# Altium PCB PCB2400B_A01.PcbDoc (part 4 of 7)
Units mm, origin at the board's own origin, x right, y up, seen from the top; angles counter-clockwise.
Board outline 115 x 60 mm, 6 copper layers (Top Layer, Signal Layer 2, Signal Layer 3, Signal Layer 4, Signal Layer 5, Bottom Layer), stack 1.555 mm thick; 382 components, 308 nets, 1384 pads, 1152 vias.
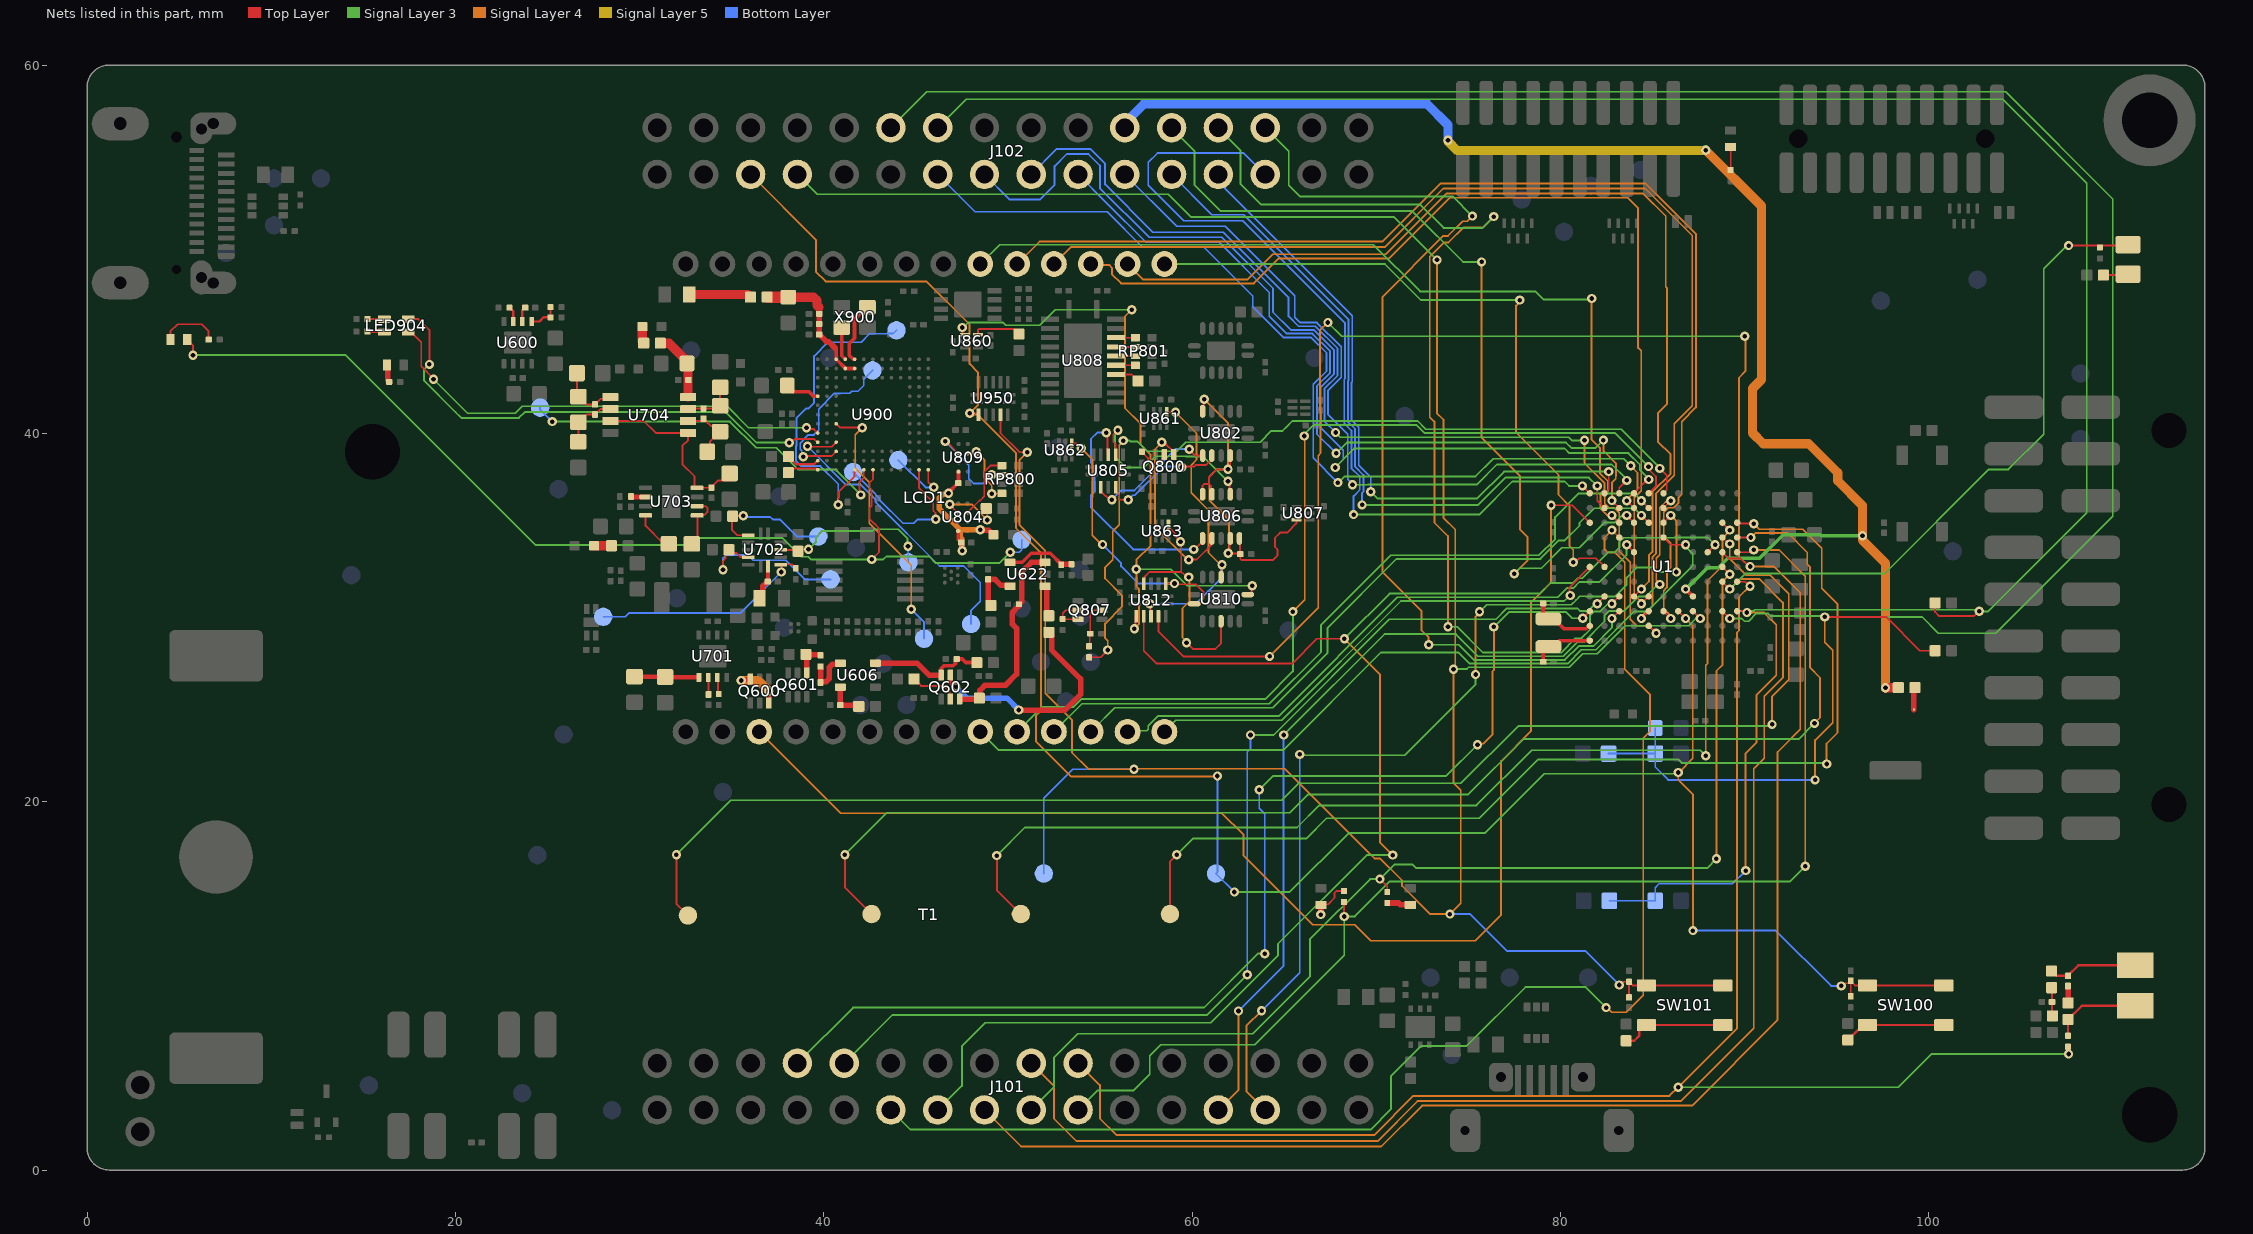
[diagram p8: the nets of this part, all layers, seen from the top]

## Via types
v1: diameter 0.5, hole 0.25, Top Layer to Bottom Layer, tented both sides, 773 vias
v2: diameter 0.508, hole 0.25, Top Layer to Bottom Layer, tented both sides, 379 vias

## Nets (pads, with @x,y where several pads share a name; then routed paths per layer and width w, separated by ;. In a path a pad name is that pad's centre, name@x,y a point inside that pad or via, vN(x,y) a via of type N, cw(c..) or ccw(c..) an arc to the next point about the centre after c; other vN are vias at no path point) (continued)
LCD_SEG14: LCD1.3 U1.C1 | length 72.1
  Top Layer w0.1: v1(79.5,36.1) 80.65,36.1 U1.C1@81.6,35.15
  Signal Layer 4 w0.1: LCD1.3@36.5,23.8 40.925,19.375 61.625,19.375 62.8,18.2 62.8,17.075 66.556,13.319 68.831,13.319 69.697,12.453 75.371,12.453 76.783,13.864 76.783,22.208 78.4,23.825 78.4,30.812 79.5,31.912 v1(79.5,36.1)
LCD_SEG28: LCD1.9 U1.D6 | length 46.4
  Top Layer w0.1: U1.D6@85.6,34.35 86.001,33.951 v1@86.799,33.951 ; v1(86.801,33.95) v1@86.799,33.951 ; v1@86.801,33.951 v1@86.799,33.951
  Signal Layer 3 w0.1: LCD1.9@48.5,23.8 49.493,22.807 64.957,22.807 70.261,28.111 74.464,28.111 75.075,27.5 80.392,27.5 81.142,28.25 81.935,28.25 84.023,30.338 84.713,30.338 87.189,32.814 87.189,33.464 86.801,33.852 v1(86.801,33.95)
LCD_SEG29: LCD1.10 U1.A5 | length 51.2
  Top Layer w0.1: v1(84.789,38.2) 84.7,38.2 84.7,38.15 85.189,37.661 85.189,37.139 U1.A5@84.8,36.75
  Signal Layer 3 w0.1: LCD1.10@50.5,23.8 51.843,25.143 53.56,25.143 53.992,25.575 63.975,25.575 65.475,27.075 v1(65.475,30.325) ; v1(66.098,39.859) 66.098,39.948 66.613,40.463 72.178,40.463 72.613,40.027 82.961,40.027 v1(84.789,38.2)
  Signal Layer 4 w0.1: v1(65.475,30.325) 66.118,30.968 66.118,39.84 v1(66.098,39.859)
LCD_SEG30: LCD1.11 U1.B5 | length 39.7
  Top Layer w0.1: v1(84.4,36.35) U1.B5@84.8,35.95 ; v1(84.4,36.35) 84.469,36.282 v1@84.464,36.295
  Signal Layer 3 w0.1: LCD1.11@52.5,23.8 54.025,25.325 64.2,25.325 67.005,28.13 67.005,29.601 70.79,33.386 78.836,33.386 79.711,34.261 79.711,35.46 80.991,36.74 84.01,36.74 v1(84.4,36.35)
LCD_SEG31: LCD1.12 U1.C5 | length 36.4
  Top Layer w0.1: v1(84.4,35.55) U1.C5@84.8,35.15
  Signal Layer 3 w0.1: LCD1.12@54.575,23.95 54.65,23.95 55.8,25.1 64.375,25.1 67.347,28.072 67.347,29.43 71.103,33.186 78.919,33.186 79.922,34.189 80.239,34.189 81.039,34.989 81.039,35.139 81.839,35.939 84.011,35.939 v1(84.4,35.55)
LCD_SEG32: LCD1.13 U1.E4 | length 32.6
  Top Layer w0.1: v1(83.6,33.95) U1.E4@84,33.55 ; v1(83.6,33.95) 83.669,33.882 83.815,33.735
  Signal Layer 3 w0.1: LCD1.13@56.5,23.8 56.552,23.852 57.552,23.852 57.625,23.925 57.625,24.125 57.7,24.2 ; 57.699,24.201 58.148,24.65 64.7,24.65 71.15,31.1 79.85,31.1 80.35,31.6 80.701,31.6 81.04,31.939 82.14,31.939 83.6,33.4 v1(83.6,33.95)
LCD_SEG33: LCD1.14 U1.F1 | length 27.1
  Top Layer w0.1: v1(80.539,31.2) 80.5,31.2 80.5,31.65 U1.F1@81.6,32.75
  Signal Layer 3 w0.1: LCD1.14@58.5,23.8 59.125,24.425 64.871,24.425 71.346,30.9 80.2,30.9 80.5,31.2 v1(80.539,31.2)
LCD_SEG34: LCD1.15 U1.F2 | length 37.7
  Top Layer w0.1: v1(80.7,33) 80.8,33 81.023,33.223 81.927,33.223 U1.F2@82.4,32.75
  Signal Layer 3 w0.1: LCD1.15@58.5,49.2 70.475,49.2 72.434,47.241 v1(77.794,47.241)
  Signal Layer 4 w0.1: v1(77.794,47.241) 77.794,47.133 77.6,46.939 77.6,40.05 79.9,37.75 79.9,36.676 80.494,36.082 80.494,33.9 80.7,33.694 v1(80.7,33)
LCD_SEG35: LCD1.16 U1.H4 | length 54
  Top Layer w0.1: U1.H4@84,31.15 v1(84.4,31.549)
  Signal Layer 4 w0.1: LCD1.16@56.5,49.2 57.35,48.35 63,48.35 64.384,49.734 70.509,49.734 73.8,53.025 84.504,53.025 85.723,51.806 85.723,47.968 85.789,47.902 85.789,41.589 85.3,41.1 85.3,39.55 85.985,38.865 85.985,37.818 85,36.833 85,33.568 84.81,33.378 84.81,31.959 v1(84.4,31.549)
LCD_SEG36: LCD1.17 U1.H5 | length 55
  Top Layer w0.1: v1@84.4,30.75 U1.H5@84.8,31.15
  Signal Layer 4 w0.1: LCD1.17@54.5,49.2 54.552,49.148 55.502,49.148 55.65,49 55.65,48.65 56.15,48.15 63.36,48.15 64.711,49.501 70.701,49.501 74,52.8 83.653,52.8 84.222,52.231 84.222,44.646 84.389,44.479 84.389,36.895 84.011,36.517 84.011,31.236 84.4,30.846 v1(84.4,30.749)
LCD_SEG37: LCD1.18 U1.J5 | length 59.9
  Top Layer w0.1: v1(84.4,29.949) 84.8,30.349 U1.J5@84.8,30.35
  Signal Layer 4 w0.1: LCD1.18@52.5,49.2 53.42,50.12 70.47,50.12 73.65,53.3 84.609,53.3 87.161,50.749 87.161,41.494 86.185,40.518 86.185,37.735 85.2,36.75 85.2,33.485 85.01,33.295 85.01,30.653 84.4,30.043 v1(84.4,29.949)
LCD_SEG38: LCD1.19 U1.J6 | length 62.6
  Top Layer w0.1: U1.J6@85.6,30.35 v1(86.001,29.949)
  Signal Layer 4 w0.1: LCD1.19@50.5,49.2 51.715,50.415 70.34,50.415 73.5,53.575 84.617,53.575 87.361,50.831 87.361,41.411 86.589,40.639 86.589,36.688 86.412,36.511 86.412,36.211 86.162,35.961 85.862,35.961 85.612,35.711 85.612,34.408 85.988,34.032 85.988,32.729 85.789,32.53 85.789,31.639 85.612,31.462 85.612,30.477 86.001,30.088 v1(86.001,29.949)
LCD_SEG39: LCD1.20 U1.K5 | length 55.8
  Top Layer w0.1: U1.K5@84.799,29.552 U1.K5@84.801,29.551 ; U1.K5@84.8,29.55 v1(85.2,29.149)
  Signal Layer 3 w0.1: LCD1.20@48.5,49.2 49.55,50.25 69.85,50.25 72.387,47.713 78.637,47.713 79.075,47.275 81.65,47.275 v1(81.7,47.325)
  Signal Layer 4 w0.1: v1(81.7,47.325) 81.7,39.659 82.145,39.214 82.145,37.838 82.589,37.394 82.589,36.867 82.412,36.69 82.412,36.19 82.639,35.962 82.938,35.962 83.2,35.7 83.2,33.6 83.8,33 83.8,29.9 84.14,29.56 84.789,29.56 v1(85.2,29.149)
LED_JLINK: LED901.2 TPJ912.1 U900.A7 | length 57.3
  Top Layer w0.1: U900.A7@42.675,38.025 42.675,37.52 42.496,37.342 42.496,37.01 42.6,36.907 42.6,36.064 42.496,35.96 42.496,35.345 42.726,35.115 42.738,35.115 43,34.854 43,33.55 42.74,33.29 42.74,33.234 v2@42.749,33.226
  Top Layer w0.102: LED901.2@5.43,45.11 5.75,44.79 v1(5.75,44.25)
  Signal Layer 3 w0.1: v1@5.775,44.275 5.8,44.25 14.042,44.25 24.342,33.95 32.525,33.95 32.893,34.318 37.769,34.318 38.785,33.302 39.152,33.302 39.297,33.157 v2(42.607,33.157) 43.233,33.157 43.394,33.318 45.719,33.318 46.079,32.957 49.537,32.957 v1(50.13,33.55)
  Bottom Layer w0.1: v1(50.13,33.55) 50.624,33.55 50.757,33.683 50.757,34.218 TPJ912.1@50.75,34.225 TPJ912.1@50.75,34.17
LED_STATUS_G: LED904.3 U900.D13 | length 27.5
  Top Layer w0.1: LED904.3@17.439,46.21 17.99,46.21 18.585,45.615 v1(18.585,43.749) ; v2(38.132,39.5) 38.243,39.5 38.433,39.69 39.487,39.69 39.652,39.525 U900.D13@39.675,39.525
  Signal Layer 3 w0.1: v1(18.585,43.749) 18.288,43.452 18.288,42.876 20.003,41.161 20.322,40.842 23.45,40.842 23.769,41.161 34.689,41.161 36.35,39.5 v2(38.132,39.5)
LED_STATUS_R: LED904.4 U900.E13 | length 25.6
  Top Layer w0.1: LED904.4@17.439,45.51 17.589,45.51 17.739,45.36 18.144,44.955 18.144,43.64 18.81,42.974 v1(18.81,42.939) ; v2(39.065,40.31) 39.143,40.232 39.468,40.232 U900.E13@39.675,40.025
  Signal Layer 3 w0.1: v1(18.81,42.939) 20.275,41.474 20.655,41.094 23.238,41.094 23.618,41.474 23.94,41.474 34.751,41.474 35.915,40.31 v2(39.065,40.31)
LES_LC_SENSE: J101.20 R196.1 U1.G11 | length 88.3
  Top Layer w0.1: U1.G11@89.6,31.95 90.05,31.95 v1(90.3,31.7) ; R196.1@107.568,6.693 107.584,6.677 107.584,6.316 v1(107.6,6.3)
  Signal Layer 3 w0.1: v1(86.4,4.5) 98.35,4.5 100.15,6.3 v1(107.6,6.3)
  Signal Layer 4 w0.1: J101.20@53.81,5.802 55,4.612 55,2.8 55.9,1.9 69.9,1.9 72.023,4.023 85.923,4.023 v1(86.4,4.5) 89.6,7.7 89.6,29.2 89.7,29.3 89.7,31.122 90.278,31.7 v1(90.3,31.7)
LES_LIGHT_EXCITE: Q100.1 R307.2 | length 1.3
  Top Layer w0.1: R307.2@109.55,48.6 110.775,48.6 Q100.1@110.825,48.65
LES_LIGHT_SENSE: J101.18 Q100.2 R199.1 U1.G10 | length 107.6
  Top Layer w0.1: U1.G10@88.8,31.95 v1(89.201,31.549) ; v1(107.6,50.2) 110.775,50.2 Q100.2@110.825,50.25
  Signal Layer 3 w0.1: v1@89.201,31.601 v1(89.201,31.549) 90.039,32.388 97.602,32.388 103.257,38.043 104.333,38.043 106.25,39.96 106.25,48.95 107.5,50.2 v1(107.6,50.2)
  Signal Layer 4 w0.1: J101.18@51.27,5.802 52.5,4.572 52.5,2.8 53.725,1.575 70.074,1.575 72.244,3.745 86.545,3.745 90.5,7.7 90.5,21.789 91.071,22.36 91.071,25.722 ; v1(89.201,31.549) 89.752,32.1 90.8,32.1 92.088,30.812 92.088,26.739 91.071,25.722 ; 91.326,25.977 91.071,25.722
LFXTAL_N: C422.1 U1.L1 X2.1 | length 3.3
  Top Layer w0.2: C422.1@79.075,27.6 79.075,28.15 X2.1@79.35,28.425 ; X2.1@79.375,28.435 79.66,28.435 79.975,28.75 U1.L1@81.6,28.75
LFXTAL_P: C421.1 U1.K1 X2.2 | length 3.5
  Top Layer w0.2: C421.1@79.075,30.775 79.075,30.2 X2.2@79.35,29.925 79.677,29.925 80.202,29.4 81.409,29.4 81.559,29.55 U1.K1@81.6,29.55
MCU_PB9: C102.1 J102.5 R100.1 SW100.3 SW100.4 TPJ652.1 U1.J7 U950.8 | length 120.2
  Top Layer w0.1: v2(47.921,41.089) 48.35,41.089 48.4,41.039 U950.8@48.4,41.015 ; U1.J7@86.4,30.35 v1(86.801,29.949) ; v1(95.25,10) 95.358,10 95.501,10.143 95.659,10.143 C102.1@95.769,10.253 ; C102.1@95.767,10.275 C102.1@95.769,10.273 C102.1@95.769,10.253 ; R100.1@95.769,9.435 C102.1@95.769,10.253 ; SW100.3@100.825,10.023 SW100.4@96.675,10.023 95.999,10.023 C102.1@95.769,10.253
  Signal Layer 3 w0.1: J102.5@36.03,54.062 J102.5@36.056,54.062 ; v1(62.3,15.1) 65.3,15.1 68.5,18.3 75.9,18.3 79.12,21.52 86.334,21.52 v1(86.399,21.585)
  Signal Layer 4 w0.1: J102.5@36.03,54.062 39.575,50.517 39.575,48.787 40.104,48.258 45.578,48.258 47.921,45.915 47.921,43.774 48.369,43.325 48.369,41.536 v2(47.921,41.089) ; v2@47.898,41.065 47.943,41.02 48.359,41.02 50.435,38.944 50.435,34.865 51.8,33.5 51.8,24.95 51.534,24.684 51.534,23.266 53.425,21.375 61.35,21.375 v1(61.375,21.4) ; v1(86.801,29.949) 87.189,29.56 87.189,22.352 86.423,21.585 v1(86.399,21.585) 86.399,21.201 87.2,20.4 v1(87.2,13)
  Bottom Layer w0.1: v1(61.375,21.4) 61.375,16.175 TPJ652.1@61.3,16.1 v1(62.3,15.1) ; v1(87.2,13) 91.706,13 94.706,10 v1(95.25,10)
MCU_PB10: C103.1 J102.7 R101.1 SW101.3 SW101.4 TPJ653.1 U1.J8 U950.11 | length 160.1
  Top Layer w0.1: U950.11@49.6,41.015 49.6,40.019 50.644,38.975 v2(51.05,38.975) ; v1(83.2,10.05) 83.272,10.05 83.443,10.221 R101.1@83.736,10.221 ; C103.1@83.727,9.374 83.731,9.378 83.731,10.216 R101.1@83.736,10.221 ; U1.J8@87.2,30.35 v1(87.601,29.949) ; SW101.3@88.825,10.023 SW101.4@84.675,10.023 83.924,10.023 83.736,10.211 R101.1@83.736,10.221
  Signal Layer 3 w0.1: J102.7@38.57,54.062 39.643,52.989 58.711,52.989 59.95,51.75 70.975,51.75 v1(73.3,49.425) ; v1(74.2,27.2) 74.911,27.2 75.011,27.3 80.475,27.3 81.214,28.039 82.007,28.039 83.528,29.56 86.962,29.56 87.351,29.949 v1(87.601,29.949)
  Signal Layer 4 w0.1: v2(51.05,38.975) 50.635,38.56 50.635,35.021 52.025,33.631 52.025,25.894 53.475,24.444 53.475,22.675 54.386,21.764 v1(56.847,21.764) 56.872,21.789 65.044,21.789 69.654,17.179 69.908,16.925 70.2,16.925 71.4,15.725 71.4,15.433 72.933,13.9 v1(74,13.9) 74.589,14.489 74.589,20.617 74.2,21.006 v1(74.2,27.2) 74.2,27.308 74.289,27.397 74.289,34.782 73.647,35.424 73.647,40.757 73.3,41.104 v1(73.3,49.425)
  Bottom Layer w0.1: TPJ653.1@51.95,16.1 51.95,20.2 53.514,21.764 v1(56.847,21.764) ; v1(74,13.9) 75.1,13.9 77.1,11.9 81.35,11.9 v1(83.2,10.05)
MCU_PB15: J101.11 U1.D3 | length 73.8
  Top Layer w0.1: v1(82.801,34.75) U1.D3@83.2,34.35
  Signal Layer 3 w0.102: J101.11@43.65,3.262 44.712,2.2 69.7,2.2 70.8,3.3 70.8,5.1 72.438,6.738 74.91,6.738 78.107,9.935 81.369,9.935 v1(82.483,8.821)
  Signal Layer 4 w0.1: v1(82.801,34.75) 82.4,34.349 82.4,33.7 82.562,33.538 82.962,33.538 83.5,33 83.5,27.2 84.864,25.836 84.864,23.814 84.5,23.45
  Signal Layer 4 w0.102: v1@82.547,8.821 82.799,8.568 83.573,8.568 84.5,9.495 84.5,23.45
MCU_PC1: J101.8 U1.J1 | length 62.5
  Top Layer w0.1: v1(81.215,29.964) U1.J1@81.6,30.35
  Signal Layer 3 w0.1: J101.8@38.57,5.802 41.593,8.825 60.65,8.825 63.575,11.75 v1(63.95,11.75) ; v1(63.65,20.65) 64.4,21.4 73.8,21.4 v1(75.5,23.1) ; v1(76.389,29.493) 76.404,29.493 77.21,30.3 80.319,30.3 80.655,29.964 v1(81.215,29.964)
  Signal Layer 4 w0.1: v1(75.5,23.1) 75.549,23.149 75.817,23.149 76.311,23.643 76.311,27.072 76.389,27.15 v1(76.389,29.493)
  Bottom Layer w0.1: v1(63.65,20.65) 63.65,19.65 63.95,19.35 v1(63.95,11.75)
MCU_PC2: J101.10 U1.H2 | length 59.5
  Top Layer w0.1: v1(82,30.749) U1.H2@82.4,31.15
  Signal Layer 3 w0.1: J101.10@41.11,5.802 43.733,8.425 60.825,8.425 v1(63,10.6) ; v1(63.175,23.625) 64.425,23.625 70.711,29.911 76.506,29.911 77.095,30.5 80.932,30.5 81.079,30.352 81.376,30.352 81.39,30.338 81.481,30.338 81.893,30.749 v1(82,30.749)
  Bottom Layer w0.1: v1(63,10.6) 63,22.7 63.175,22.875 v1(63.175,23.625)
MCU_PC8: T1.1 U1.D10 | length 78.9
  Top Layer w0.1: v1@32.025,17.152 32,17.127 v1(32,17.125) 32,14.448 T1.1@32.624,13.824 ; U1.D10@88.8,34.35 89.175,33.975 89.2,33.951 v1(89.2,34)
  Signal Layer 3 w0.1: v1(32,17.125) 34.957,20.082 64.882,20.082 65.8,21 74.6,21 77.711,24.111 91.411,24.111 v1(91.5,24.2)
  Signal Layer 4 w0.1: v1(89.2,34) 89.2,33.2 90.1,32.3 91.4,32.3 92.4,31.3 92.4,26.619 91.5,25.719 v1(91.5,24.2)
MCU_PC9: T1.2 U1.D11 | length 73.5
  Top Layer w0.1: v1(41.15,17.125) 41.15,15.35 T1.2@42.6,13.9 ; U1.D11@89.6,34.35 v1(90.35,34.35)
  Signal Layer 3 w0.1: v1(41.15,17.125) 43.425,19.4 65.3,19.4 66.3,20.4 75,20.4 78,23.4 92.943,23.4 93.796,24.253 v1(93.8,24.253)
  Signal Layer 4 w0.1: v1(90.35,34.35) 90.6,34.6 92.345,34.6 93.411,33.534 93.411,32.889 93.562,32.738 93.562,27.272 94.1,26.734 94.1,24.557 93.8,24.258 v1(93.8,24.253)
MCU_PC10: T1.3 U1.C10 | length 58.1
  Top Layer w0.1: v1(49.4,17.075) 49.4,15.2 T1.3@50.7,13.9 ; U1.C10@88.8,35.15 v1(89.201,34.75)
  Signal Layer 3 w0.1: v1(49.4,17.075) 50.925,18.6 65.7,18.6 66.9,19.8 75.445,19.8 78.445,22.8 87.6,22.8 v1(87.9,22.5)
  Signal Layer 4 w0.1: v1(87.9,22.5) 87.9,27.4 87.99,27.49 87.99,31.99 88.8,32.8 88.8,34.305 89.201,34.706 v1(89.201,34.75)
MCU_PC11: T1.4 U1.C11 | length 58.4
  Top Layer w0.1: T1.4@58.8,13.9 58.8,16.75 v1(59.175,17.125) ; U1.C11@89.6,35.15 89.65,35.1 v1(90.5,35.1)
  Signal Layer 3 w0.1: v1(59.175,17.125) 60.05,18 66.2,18 67.3,19.1 75.6,19.1 78.798,22.298 86.395,22.298 86.588,22.105 94.409,22.105 v1(94.464,22.05)
  Signal Layer 4 w0.1: v1(90.5,35.1) 90.8,34.8 93.171,34.8 94.199,33.773 94.199,31.585 95.058,30.726 95.058,23.759 94.46,23.161 94.46,22.054 v1(94.464,22.05)
MCU_PD3: C250.1 J102.12 R240.2 R241.1 R245.1 U1.J10 | length 142
  Top Layer w0.1: U1.J10@88.8,30.35 v1(89.201,29.949) ; v1(94.356,30.039) 97.689,30.039 99.528,28.2 R241.1@100.35,28.2
  Signal Layer 3 w0.1: J102.12@43.65,56.602 45.604,58.556 104.175,58.556 110,52.731 110,35.5 103.65,29.15 100.528,29.15 99.64,30.039 v1(94.356,30.039) ; v1(89.201,29.949) 89.851,29.949 90,29.8 90.221,29.8 90.649,30.227 91.273,30.227 91.413,30.087 94.311,30.087 v1@94.356,30.042
  Signal Layer 4 w0.1: v1@93.691,21.126 93.75,21.068 93.833,21.068 v1@93.978,21.213 ; v1(93.836,21.187) 93.836,23.347 ; 94.074,23.585 93.836,23.347 ; v1(94.356,30.039) 94.356,28.656 94.788,28.224 94.788,24.3 93.836,23.347
  Bottom Layer w0.1: R240.2@82.618,22.617 R245.1@85.151,22.617 ; C250.1@85.151,24.003 R245.1@85.151,22.617 ; v1(93.836,21.187) 85.85,21.187 85.151,21.886 R245.1@85.151,22.617
MCU_PD4: J102.14 R242.1 R243.1 R244.2 U1.J11 | length 131.7
  Top Layer w0.1: U1.J11@89.6,30.35 90.056,30.35 v1(90.129,30.276) ; R242.1@100.35,30.8 100.35,30.303 100.575,30.078 102.448,30.078 102.709,30.339 v1(102.753,30.339)
  Signal Layer 3 w0.1: J102.14@46.19,56.602 47.738,58.15 104.016,58.15 108.589,53.577 108.589,35.689 103.239,30.339 102.645,30.339 102.556,30.427 90.566,30.427 90.492,30.353 90.206,30.353 v1(90.129,30.276)
  Signal Layer 4 w0.1: v1(90.063,16.263) 90.063,22.626 90.657,23.22 90.657,25.803 91.725,26.871 91.725,29.602 91.05,30.276 v1(90.129,30.276)
  Bottom Layer w0.1: R244.2@82.663,14.625 R243.1@85.151,14.625 ; R243.1@85.149,14.623 R243.1@85.151,14.625 ; v1(90.063,16.263) 89.343,15.543 85.356,15.543 85.151,15.338 R243.1@85.151,14.625
MCU_PD8: J102.22 R246.1 U1.H8 | length 81
  Top Layer w0.203: v1(86.801,31.549) U1.H8@87.2,31.15
  Top Layer w0.5: v1(97.659,26.19) 98.34,26.19 R246.1@98.35,26.2
  Signal Layer 3 w0.203: v1(86.801,31.549) 86.823,31.549 87.984,32.71 88.584,32.71 89.091,33.217 90.817,33.217 92.1,34.5 94.109,34.5 94.166,34.443 v1(96.407,34.443)
  Signal Layer 3 w0.5: v1@87.875,55.4 v1(87.9,55.375)
  Signal Layer 4 w0.5: v1(87.9,55.375) 90.925,52.35 90.925,42.93 90.432,42.437 90.432,40.024 91.018,39.438 93.483,39.438 95.06,37.861 95.06,37.429 96.407,36.082 v1(96.407,34.443) 96.407,34.207 97.659,32.955 v1(97.659,26.19)
  Signal Layer 5 w0.5: v1(73.899,55.917) 73.899,55.862 74.404,55.357 87.882,55.357 v1(87.9,55.375)
  Bottom Layer w0.5: J102.22@56.35,56.602 56.35,56.841 57.409,57.9 72.744,57.9 73.899,56.745 v1(73.899,55.917)
MCU_PD13: J102.24 U1.C4 | length 47.3
  Top Layer w0.1: v1(83.6,35.55) U1.C4@84,35.15
  Signal Layer 3 w0.1: J102.24@58.89,56.602 58.89,56.574 60.125,55.339 60.125,53.5 61.55,52.075 71.95,52.075 74.713,49.312 v1(75.725,49.312) ; v1(77.5,32.375) 77.803,32.678 78.315,32.678 78.976,32.678 80.087,33.789 81.021,33.789 82.393,35.161 82.961,35.161 83.35,35.55 v1(83.6,35.55)
  Signal Layer 4 w0.1: v1(75.725,49.312) 75.725,39.775 77.8,37.7 77.8,34.8 78.211,34.389 78.211,33.086 v1(77.5,32.375) ; v1@83.6,35.499 v1(83.6,35.55) v1@83.6,35.582
MCU_PD14: J102.26 U1.H3 | length 55
  Top Layer w0.1: v1(82.8,30.75) U1.H3@83.2,31.15
  Signal Layer 3 w0.1: J102.26@61.43,56.602 61.43,56.574 62.625,55.379 62.625,53.55 63.75,52.425 72.4,52.425 73.664,51.161 75.775,51.161 v1(76.389,51.775) ; v1(73.9,29.5) 74.4,29.5 75.8,28.1 80.05,28.1 80.817,28.867 81.142,28.867 81.611,29.336 81.611,30.11 81.839,30.338 82.175,30.338 82.587,30.75 v1(82.8,30.75)
  Signal Layer 4 w0.1: v1(73.9,29.5) 73.9,34.425 73.161,35.164 73.161,40.639 72.911,40.889 72.911,49.586 73.7,50.375 73.925,50.375 74.75,51.2 75.814,51.2 v1(76.389,51.775)
MCU_PD15: J102.28 U1.J3 | length 53
  Top Layer w0.1: v1(82.8,29.95) U1.J3@83.2,30.35
  Signal Layer 3 w0.1: J102.28@63.97,56.602 65.25,55.322 65.25,53.475 65.85,52.875 74.15,52.875 v1(75.225,51.8) ; v1(72.855,28.521) 74.473,28.521 75.294,27.7 80.25,27.7 81,28.45 81.8,28.45 82.8,29.45 v1(82.8,29.95)
  Signal Layer 4 w0.1: v1(72.855,28.521) 72.846,28.53 72.846,28.921 72.468,29.299 72.468,30.348 70.35,32.466 70.35,47.425 73.65,50.725 73.9,50.725 74.7,51.525 74.95,51.525 v1(75.225,51.8)
MCU_PE0: J101.13 U1.E9 U812.2 | length 81.8
  Top Layer w0.1: U812.2@57.375,30.065 57.375,28.2 58.074,27.501 65.433,27.501 66.782,28.85 68.2,28.85 v1@68.225,28.825 ; U1.E9@88,33.55 88.001,33.55 v1(88.401,33.95)
  Signal Layer 3 w0.1: J101.13@46.19,3.262 47.5,4.572 47.5,6.725 48.775,8 61.025,8 64.664,11.638 64.664,12.275 69.489,17.1 70.125,17.1 v1(70.9,17.1) ; v1(68.275,28.85) 70.725,31.3 78.888,31.3 79.466,31.878 80.681,31.878 80.942,32.139 81.189,32.139 82.6,33.55 82.951,33.55 83.211,33.811 83.211,34.111 83.439,34.338 86.188,34.338 86.2,34.35 88,34.35 v1(88.401,33.95)
  Signal Layer 4 w0.1: v1(68.275,28.85) 70.2,26.925 70.2,17.8 v1(70.9,17.1)
MCU_PE1: J101.15 U1.E10 U812.4 | length 138.4
  Top Layer w0.1: U812.4@58.175,30.065 58.175,29.25 59.535,27.89 64.165,27.89 v1@64.175,27.9 ; U1.E10@88.8,33.55 89.149,33.2 89.8,33.2 90.223,32.777 v1(90.304,32.777)
  Signal Layer 3 w0.1: v1(67.375,46.025) 68.125,45.275 v1(90.011,45.275)
  Signal Layer 4 w0.1: J101.15@48.73,3.262 50.714,1.278 70.272,1.278 72.495,3.501 87.151,3.501 91.8,8.15 91.8,22.7 93.028,23.928 93.028,31.347 91.598,32.777 v1(90.304,32.777) 90.223,32.777 89.7,33.3 89.7,43.025 90.05,43.375 90.05,45.275 v1(90.011,45.275) ; v1(64.21,27.89) 64.218,27.89 66.85,30.522 66.85,38.796 66.975,38.922 66.975,41.187 66.942,41.22 66.942,45.592 v1(67.375,46.025)
MCU_PE2: J101.17 R106.2 U1.F10 | length 62.3
  Top Layer w0.1: v1(70.2,15.8) 70.6,15.4 R106.2@70.6,15.1 ; U1.F10@88.8,32.75 88.8,32.748 89.198,32.35 v1(89.2,32.35)
  Signal Layer 3 w0.1: J101.17@51.27,3.262 52.5,4.492 52.5,6.1 53.8,7.4 63.299,7.4 66.402,10.503 66.402,12.537 69.665,15.8 v1(70.2,15.8) 70.989,16.589 71.986,16.589 72.175,16.4 87.975,16.4 v1(88.475,16.9)
  Signal Layer 4 w0.1: v1(88.475,16.9) 88.475,27.1 88.812,27.437 88.812,31.962 v1(89.2,32.35)
MCU_PE3: J101.19 R107.2 U1.E11 | length 67.7
  Top Layer w0.1: R107.2@68.25,14.55 68.257,14.543 68.257,13.777 v1(68.264,13.77) ; U1.E11@89.6,33.55 90.45,33.55 90.504,33.605 v1(90.504,33.677)
  Signal Layer 3 w0.1: J101.19@53.81,3.262 54.875,4.327 56.827,4.327 57.7,5.2 57.7,6.2 58.3,6.8 63.4,6.8 68.264,11.664 v1(68.264,13.77) 68.846,13.77 70.748,15.672 92.472,15.672 v1(93.3,16.5)
  Signal Layer 4 w0.1: v1(90.504,33.677) 91.873,33.677 93.3,32.25 v1(93.3,16.5)
MCU_PE8: J102.13 U1.B4 | length 52.7
  Top Layer w0.1: v1@83.671,36.279 U1.B4@84,35.95
  Signal Layer 3 w0.1: v1(67.923,37.332) 67.954,37.332 68.287,37.665 75.393,37.665 76.353,38.625 83.45,38.625 v1(83.825,38.25)
  Signal Layer 4 w0.1: v1(83.6,36.35) 83.6,36.389 84.189,36.978 84.189,37.861 83.825,38.225 v1(83.825,38.25)
  Bottom Layer w0.1: J102.13@46.19,54.062 48.213,52.038 55.387,52.038 57.3,50.125 60.638,50.125 63.3,47.463 63.3,46.875 64.957,45.218 66.451,45.218 67.3,44.369 67.3,43.38 66.586,42.666 66.586,38.669 v1(67.923,37.332)
MCU_PE9: J102.15 U1.A4 | length 54.1
  Top Layer w0.1: U1.A4@84,36.75 84.191,36.942 ; U1.A4@84,36.75 84.75,37.5 v1(84.8,37.5)
  Signal Layer 3 w0.1: v1(67.779,38.151) 68.814,39.186 80.226,39.186 80.481,38.931 83.694,38.931 84.311,38.314 84.311,38.039 84.8,37.55 v1(84.8,37.5)
  Bottom Layer w0.1: J102.15@48.73,54.062 50.091,52.701 51.726,52.701 52.54,53.515 52.54,54.515 53.2,55.175 54.375,55.175 55,54.55 55,53.325 57.675,50.65 61.625,50.65 64.396,47.879 64.396,46.579 65.357,45.618 66.617,45.618 67.7,44.535 67.7,43.214 66.986,42.5 66.986,40.311 67.983,39.314 67.985,39.314 68.213,39.086 68.213,38.585 v1(67.779,38.151)
MCU_PE10: J102.17 U1.C3 | length 47.3
  Top Layer w0.1: v1(82.8,35.55) U1.C3@83.2,35.15
  Signal Layer 3 w0.1: v1(67.797,40.05) 68.058,39.789 80.451,39.789 80.615,39.625 v1(81.311,39.625)
  Signal Layer 4 w0.1: v1(81.311,39.625) 81.311,38.389 82.389,37.311 82.389,36.95 82.175,36.736 82.175,35.925 82.55,35.55 v1(82.8,35.55)
  Bottom Layer w0.1: J102.17@51.27,54.062 52.658,55.45 54.475,55.45 55.275,54.65 55.275,53.525 57.875,50.925 61.7,50.925 65.246,47.379 65.246,46.354 65.782,45.818 66.7,45.818 67.9,44.618 67.9,43.131 67.186,42.417 67.186,40.661 v1(67.797,40.05)
MCU_PE11: J102.19 U1.B3 | length 44
  Top Layer w0.1: v1(82.8,36.351) U1.B3@83.2,35.95
  Signal Layer 3 w0.1: v1(67.824,38.925) 68.4,39.501 80.307,39.501 80.608,39.2 81.9,39.2 v1(82.339,39.639)
  Signal Layer 4 w0.1: v1(82.339,39.639) 82.35,39.639 82.35,39.046 83.014,38.383 83.014,37.696 83.011,37.694 83.011,37.536 82.8,37.325 v1(82.8,36.351)
  Bottom Layer w0.1: J102.19@53.81,54.062 55.34,52.532 57.472,50.4 61.45,50.4 64.196,47.654 64.196,46.354 65.132,45.418 66.534,45.418 67.5,44.452 67.5,43.297 66.786,42.583 66.786,39.963 v1(67.824,38.925)
MCU_PE12: J102.21 U1.A3 | length 41.2
  Top Layer w0.1: U1.A3@83.2,36.75 83.2,37.049 v1(83.6,37.45)
  Signal Layer 3 w0.1: v1(68.715,37.215) 69.536,37.215 69.539,37.218 75.459,37.218 76.555,38.314 82.786,38.314 83.6,37.5 v1(83.6,37.45)
  Bottom Layer w0.1: J102.21@56.35,54.062 59.162,51.25 61.8,51.25 65.575,47.475 65.575,46.308 65.865,46.018 66.782,46.018 68.1,44.701 68.1,43.049 67.386,42.335 67.386,41.011 68.453,39.944 68.453,37.518 68.715,37.256 v1(68.715,37.215)
MCU_PE13: J102.23 U1.B2 | length 38.3
  Top Layer w0.1: v1(82,37.15) 82,36.349 U1.B2@82.4,35.95
  Signal Layer 3 w0.1: v1(69.237,36.117) 75.537,36.117 77.02,37.6 81.55,37.6 v1(82,37.15)
  Bottom Layer w0.1: J102.23@58.89,54.062 61.077,51.875 62.8,51.875 68.5,46.175 68.5,42.883 68.461,42.844 68.461,40.632 68.853,40.241 68.853,38.195 69.304,37.744 69.304,36.846 69.237,36.779 v1(69.237,36.117)
MCU_PE14: J102.25 U1.A2 | length 35.6
  Top Layer w0.1: U1.A2@82.4,36.75 82.625,36.975 v1(82.625,37.925)
  Signal Layer 3 w0.1: v1(69.7,36.829) 70.061,36.468 75.49,36.468 76.947,37.925 v1(82.625,37.925)
  Bottom Layer w0.1: J102.25@61.43,54.062 61.43,53.67 68.7,46.4 68.7,42.8 68.661,42.761 68.661,40.715 69.053,40.324 69.053,38.278 69.7,37.631 v1(69.7,36.829)
MCU_PE15: J102.27 U1.A1 | length 46.8
  Top Layer w0.1: v1(81.2,37.15) U1.A1@81.6,36.75
  Signal Layer 3 w0.1: v1(68.771,35.593) 75.589,35.593 77.385,37.389 80.232,37.389 80.471,37.15 v1(81.2,37.15)
  Bottom Layer w0.1: J102.27@63.97,54.062 62.807,55.225 58.123,55.225 57.625,54.727 57.625,53.475 59.55,51.55 62.75,51.55 68.3,46 68.3,42.966 68.261,42.927 68.261,40.55 68.653,40.158 68.653,38.112 69.104,37.661 69.104,36.929 68.771,36.596 v1(68.771,35.593)
MCU_PF7: R841.2 U1.A6 | length 46.6
  Top Layer w0.1: R841.2@54.411,27.845 55.031,27.845 v1(55.425,28.239) ; v1(85.396,38.1) 85.775,37.721 85.775,36.934 85.6,36.759 U1.A6@85.6,36.75
  Signal Layer 3 w0.1: v1(56.268,39.609) 56.611,39.609 56.651,39.568 ; 56.755,39.568 56.651,39.568 ; v1(85.396,38.1) 85.396,38.143 83.311,40.227 72.696,40.227 72.249,40.675 65.45,40.675 65.139,40.364 64.911,40.136 64.311,40.136 63.7,39.525 59.662,39.525 59.169,39.032 57.562,39.032 57.026,39.568 56.651,39.568
  Signal Layer 4 w0.1: v1(55.425,28.239) 55.425,28.732 55.282,28.875 55.282,29.676 56.193,30.587 56.193,31.211 55.282,32.122 55.282,32.733 55.694,33.144 55.694,34.694 56.043,35.043 56.043,39.351 56.268,39.576 v1(56.268,39.609)
MCU_PF8: J101.25 U1.B6 | length 52.7
  Top Layer w0.1: U1.B6@85.6,35.95 85.792,36.142 ; U1.B6@85.601,35.95 v1(86.001,36.35)
  Signal Layer 3 w0.1: v1@64.991,23.641 70.45,29.1 73.5,29.1 74.325,29.1 75.525,27.9 80.15,27.9 80.917,28.667 81.269,28.667 82.389,29.788 82.389,30.089 82.661,30.361 83.462,30.361 84.239,31.138 84.641,31.138 85.303,31.8 v1(85.4,31.8)
  Signal Layer 4 w0.1: J101.25@61.43,3.262 62.525,4.357 v1(62.525,8.639) ; v1(85.4,31.8) 85.21,31.99 85.21,33.212 85.4,33.402 85.4,35.966 85.71,36.275 85.926,36.275 v1(86.001,36.35)
  Bottom Layer w0.1: v1(62.525,8.639) 64.975,11.089 v1(64.975,23.625)
MCU_PF9: J101.27 U1.C6 | length 52.2
  Top Layer w0.1: U1.C6@85.6,35.15 85.792,35.342 ; U1.C6@85.601,35.15 v1(86.001,35.55)
  Signal Layer 3 w0.1: v1(65.85,22.57) 65.894,22.525 71.55,22.525 75.4,26.375 v1(75.4,26.911) ; v1(75.609,30.312) 75.997,30.7 80.6,30.7 80.85,30.95 ; 80.85,30.95 81.055,31.154 81.377,31.154 81.393,31.139 82.961,31.139 83.6,31.778 83.6,32.175 84.15,32.725 85.075,32.725 85.325,32.475 v1(86.3,32.475)
  Signal Layer 4 w0.1: v1(63.775,8.65) 62.95,7.825 62.95,4.282 J101.27@63.97,3.262 ; v1(75.4,26.911) 75.4,30.053 75.609,30.262 v1(75.609,30.312) ; v1(86.001,35.55) 86.3,35.25 v1@86.3,32.45
  Bottom Layer w0.1: v1(63.775,8.65) 65.85,10.725 v1(65.85,22.57)
N16768220: R104.1 SW100.1 SW100.2 | length 5.6
  Top Layer w0.127: R104.1@95.607,7.056 96.163,7.612 96.414,7.612 SW100.2@96.675,7.873 SW100.1@100.825,7.873
N16768338: R105.1 SW101.1 SW101.2 | length 5.8
  Top Layer w0.127: R105.1@83.574,7.02 84.015,7.02 84.276,7.281 84.276,7.611 84.537,7.873 SW101.2@84.675,7.873 SW101.1@88.825,7.873
N16769621: LED101.1 R107.1 | length 2.2
  Top Layer w0.1: LED101.1@67,14.396 67.041,14.437 67.391,14.437 67.737,14.783 67.737,15.056 67.831,15.15 R107.1@68.25,15.15
  Top Layer w0.305: v1(66.99,13.874) 66.995,13.879 66.995,14.391 LED101.1@67,14.396
N16769748: LED100.1 R106.1 | length 1.3
  Top Layer w0.305: R106.1@70.6,14.5 71.217,14.5 71.311,14.406 71.84,14.406 LED100.1@71.85,14.396
N16831167: R700.1 U701.7 | length 0.9
  Top Layer w0.1: U701.7@34.225,26.75 34.263,26.713 34.263,25.887 R700.1@34.3,25.85
N16831188: C705.1 U701.6 | length 0.9
  Top Layer w0.1: U701.6@33.725,26.75 33.738,26.738 33.738,25.837 C705.1@33.75,25.825
N16831199: R702.1 R703.2 U701.5 | length 3.5
  Top Layer w0.1: U701.5@33.213,26.738 U701.5@33.225,26.75
  Top Layer w0.254: R702.1@29.725,26.796 29.736,26.784 31.372,26.784 R703.2@31.383,26.773 31.394,26.762 33.223,26.762 33.225,26.76 U701.5@33.225,26.75
N16831281: R705.2 TP711.1 U702.11 | length 9.5
  Top Layer w0.1: R705.2@34.853,33.685 35.024,33.514 35.245,33.514 35.466,33.292 35.873,33.292 U702.11@35.89,33.275
  Top Layer w0.102: v2(34.532,32.602) 34.532,33.084 34.664,33.216 34.664,33.496 R705.2@34.853,33.685
  Bottom Layer w0.102: v2(34.532,32.602) 34.532,33.236 34.703,33.407 35.888,33.407 36.184,33.111 37.926,33.111 38.962,32.075 TP711.1@40.375,32.075
N16831285: R706.2 TP712.1 U702.8 | length 6.8
  Top Layer w0.1: v2(35.624,35.53) 35.08,35.53 R706.2@35.053,35.503 35.01,35.46 35.01,34.776 35.311,34.475 U702.8@35.77,34.475
  Bottom Layer w0.1: v2(35.624,35.53) 35.693,35.461 37.099,35.461 37.231,35.329 37.623,35.329 38.552,34.4 TP712.1@39.7,34.4
N16831289: R707.2 TP713.1 U702.3 | length 9
  Top Layer w0.1: U702.3@37.66,33.675 38.527,33.675 R707.2@38.6,33.602 38.706,33.708 v2(39.172,33.708)
  Signal Layer 3 w0.1: v2(39.172,33.708) 39.59,34.127 39.59,34.366 39.931,34.707 42.663,34.707 42.749,34.793 44.038,34.793 44.556,34.275 44.556,33.894 v1(44.575,33.875)
  Bottom Layer w0.1: v1@44.588,33.787 44.588,33.012 TP713.1@44.6,33
N16831309: R708.2 TP714.1 U702.1 | length 12
  Top Layer w0.1: v2(37.7,32.475) 37.7,32.835 U702.1@37.66,32.875 37.685,32.9 38.262,32.9 38.363,32.799 38.373,32.799 38.483,32.689 R708.2@38.483,32.679
  Bottom Layer w0.1: TP714.1@28.025,30.043 29.218,30.043 29.418,30.243 35.468,30.243 v2(37.7,32.475)
N16831821: C707.1 L702.2 U702.14 | length 1.9
  Top Layer w0.2: C707.1@36.925,31.975 36.94,31.975 36.975,32.01 U702.14@36.975,32.79
  Top Layer w0.3: L702.2@36.51,31.05 36.695,31.235 36.695,31.715 36.92,31.94 36.92,31.955 C707.1@36.925,31.96
N16846192: R808.1 U802.6 U802.12 U806.5 U806.6 U806.12 U806.13 U807.3 | length 22.1
  Top Layer w0.1: U806.6@60.575,36.7 60.575,37.175 60.65,37.25 60.925,37.25 ; U802.6@60.575,41.2 60.613,41.238 60.613,41.82 v2(60.659,41.866) ; U806.5@61.075,36.7 61.037,36.738 61.037,37.138 60.925,37.25 ; U806.12@62.075,34.3 62.037,34.262 62.037,33.562 v2(61.975,33.5) 62.003,33.472 62.591,33.472 62.597,33.478 62.597,34.278 U806.13@62.575,34.3 ; U802.12@62.075,38.8 62.075,38.285 61.95,38.16 v2(61.95,38.05) 61.344,38.05 60.925,37.631 60.925,37.25 ; R808.1@62.619,33.444 62.619,33.193 62.678,33.134 64.409,33.134 64.648,33.373 64.648,33.695 64.506,33.837 64.506,34.338 64.78,34.612 65.16,34.612 65.665,35.118 65.665,35.295 U807.3@65.68,35.31
  Signal Layer 4 w0.1: v2(60.659,41.866) 61.95,40.575 v2(61.95,38.05) 61.344,38.05 60.932,37.638 60.932,36.384 62,35.316 62,33.525 v2(61.975,33.5)
N16846231: C804.1 C810.1 L801.2 U804.A2 U809.A2 | length 8.5
  Top Layer w0.2: v2(46.775,36.75) 46.775,36.795 47.28,37.3 C810.1@47.3,37.3 47.319,37.319 47.319,37.919 U809.A2@47.325,37.925 ; U804.A2@47.3,34.7 47.3,34.233 47.45,34.083 C804.1@47.47,34.083 47.496,34.057 47.496,33.657 v2(47.522,33.631)
  Top Layer w0.3: v2(48.503,34.777) 48.542,34.737 48.963,34.737 49.2,34.5 L801.2@49.225,34.5
  Signal Layer 4 w0.3: v2(46.775,36.75) 46.735,36.71 46.482,36.71 46.275,36.503 46.275,35.902 47.4,34.777 ; v2(47.522,33.631) 47.483,33.67 47.483,34.27 47.4,34.352 47.4,34.565 47.4,34.777 ; v2(48.503,34.777) 47.612,34.777 47.4,34.777
N16846319: Q800.1 U806.10 | length 10.3
  Top Layer w0.1: v2(58.35,39.525) 58.428,39.447 58.553,39.447 59,39 Q800.1@59,38.85 ; v2(59.825,33.143) 59.835,33.153 60.253,33.153 61.037,33.937 61.037,34.262 U806.10@61.075,34.3
  Signal Layer 4 w0.1: v2(58.35,39.525) 58.35,39.494 57.982,39.126 57.982,34.918 59.791,33.109 v2(59.825,33.143)
N16846537: RP801.5 U808.21 | length 1.1
  Top Layer w0.1: U808.21@55.87,45.2 RP801.5@56.925,45.2
N16846539: RP801.6 U808.20 | length 1.1
  Top Layer w0.1: U808.20@55.87,44.7 RP801.6@56.925,44.7
N16846547: RP801.7 U808.19 | length 1.1
  Top Layer w0.1: U808.19@55.87,44.2 RP801.7@56.925,44.2
N16846551: RP801.8 U808.18 | length 1.1
  Top Layer w0.1: U808.18@55.87,43.7 RP801.8@56.925,43.7
N16846723: R805.1 U808.17 | length 1.3
  Top Layer w0.1: U808.17@55.87,43.2 56.725,43.2 R805.1@57.075,42.85
N16846896: RP800.8 U809.C1 | length 3.6
  Top Layer w0.1: U809.C1@47.825,38.925 47.85,38.95 48.225,38.95 v2@48.25,38.925 ; v2(49.125,36.725) 49.65,36.725 RP800.8@49.675,36.75
  Signal Layer 4 w0.1: v2(48.275,39) 48.735,38.54 48.735,37.57 49.125,37.18 v2(49.125,36.725)
N16846900: RP800.6 U809.C2 | length 5.7
  Top Layer w0.1: v2(46.592,39.566) v2(46.592,39.566) 46.651,39.564 47.29,38.925 U809.C2@47.325,38.925 ; v2(49.128,37.752) v2(49.128,37.752) 49.674,37.751 RP800.6@49.675,37.75
  Bottom Layer w0.1: v2(46.592,39.566) 47.875,38.282 47.875,38.1 ; 47.874,38.1 47.874,37.545 48.137,37.282 48.658,37.282 v2(49.128,37.752)
N16846924: RP800.5 U804.C1 | length 3.7
  Top Layer w0.1: U804.C1@47.8,35.7 48.457,36.357 48.488,36.357 48.718,36.587 48.718,36.618 48.718,37.918 49.05,38.25 RP800.5@49.675,38.25
N16847739: U805.10 U806.9 | length 13.4
  Top Layer w0.1: v2(55.343,40.045) 55.345,40.044 55.4,39.989 55.4,38.905 U805.10@55.45,38.855 ; v2(60.1,33.7) 60.137,33.7 60.575,34.138 U806.9@60.575,34.3
  Bottom Layer w0.1: v2(55.343,40.045) 54.852,40.044 54.514,39.706 54.514,38.384 54.7,38.198 54.7,36.85 54.5,36.65 54.5,36.002 56.802,33.7 v2(60.1,33.7)
N16847741: U805.9 U806.3 | length 10.9
  Top Layer w0.1: U805.9@55.85,38.855 55.85,39.425 55.725,39.55 55.725,39.925 v1(55.975,40.175) ; v2(61.95,37.4) 61.95,37.29 62.04,37.2 62.04,36.735 U806.3@62.075,36.7
  Signal Layer 3 w0.1: v1(55.975,40.175) 55.975,40.067 55.825,39.917 55.825,38.72 56.388,38.157 57.411,38.157 58.019,38.764 59.662,38.764 59.687,38.739 60.616,38.739 61.95,37.406 v2(61.95,37.4)
N16847743: U802.10 U805.4 | length 6.9
  Top Layer w0.1: U805.4@55.85,37.085 55.9,37.035 55.9,36.795 56.047,36.647 56.047,36.454 56.106,36.396 v2(56.54,36.396) ; v2(59.45,38.171) 59.45,38.2 60.118,38.2 60.211,38.293 60.768,38.293 61.075,38.6 U802.10@61.075,38.8
  Bottom Layer w0.1: v2(56.54,36.396) 56.787,36.643 56.893,36.643 58.45,38.2 59.45,38.2 v2(59.45,38.171)
N16847749: U802.9 U805.2 | length 7.2
  Top Layer w0.1: U805.2@55.05,37.085 55.05,36.845 55.2,36.695 55.3,36.595 55.336,36.595 55.54,36.391 v2(55.65,36.391) ; v2(59.85,39.132) 60.182,38.8 U802.9@60.575,38.8
  Bottom Layer w0.1: v2(55.65,36.391) 56.166,36.907 56.874,36.907 59.124,39.157 59.825,39.157 v2(59.85,39.132)
N16847975: R810.1 U804.C2 | length 3.7
  Top Layer w0.1: v2@46.835,36.145 46.835,36.125 46.84,36.125 47.265,35.7 U804.C2@47.3,35.7 ; R810.1@48.825,35.925 48.875,35.875 v2(48.875,35.3)
  Signal Layer 4 w0.1: v2@46.835,36.145 48.03,36.145 v2(48.875,35.3)
  other v2: 46.834,36.145
N16916520: U810.1 U812.1 U860.4 | length 36.8
  Top Layer w0.1: v2(47.528,45.752) 47.528,45.409 47.578,45.359 U860.4@47.674,45.359 ; v2(56.872,29.4) 56.925,29.453 56.925,30.015 U812.1@56.975,30.065 ; U810.1@63.025,31.25 63.133,31.25 63.225,31.342 63.225,31.675 v2(63.275,31.725)
  Signal Layer 3 w0.1: v2(47.528,45.752) 47.567,45.752 47.833,46.018 49.741,46.018 49.884,45.875 51.725,45.875 52.568,46.718 v2(56.725,46.718) ; v2(56.975,32.625) 58.844,32.625 59.744,31.725 v2(63.275,31.725)
  Signal Layer 4 w0.1: v2(56.725,46.718) 56.357,46.35 56.357,41.381 57.206,40.532 57.206,39.388 57.75,38.844 57.75,33.909 56.975,33.134 v2(56.975,32.625) 56.975,31.7 57.125,31.55 57.125,29.653 v2(56.872,29.4)
N16916530: U810.4 U812.3 U861.4 | length 16.7
  Top Layer w0.1: v2(57.7,30.75) 57.737,30.712 57.737,30.103 U812.3@57.775,30.065 ; U861.4@58.625,41.15 58.626,41.151 v2(59.101,41.151) ; U810.4@61.575,32.2 61.6,32.225 61.6,32.85 v2(61.625,32.875)
  Signal Layer 4 w0.1: v2(59.101,41.151) 60.243,40.01 60.243,38.568 59.957,38.282 59.957,36.774 60.893,35.838 60.893,33.526 61.544,32.875 v2(61.625,32.875)
  Bottom Layer w0.1: v2(57.7,30.75) 60.207,30.75 61.625,32.168 v2(61.625,32.875)
N16916558: U810.11 U812.11 U863.4 | length 13.1
  Top Layer w0.1: U812.11@57.375,31.835 57.425,31.885 57.425,32.225 57.475,32.275 ; 57.475,32.275 57.675,32.475 59.418,32.475 ; U863.4@58.725,35.05 58.725,34.875 58.775,34.825 58.825,34.825 59.059,34.592 59.059,34.441 59.418,34.082 59.418,32.475 ; v2(59.7,28.643) 59.703,28.643 60.046,28.3 61.275,28.3 61.575,28.6 U810.11@61.575,29.8 ; v2(59.825,32.2) 59.715,32.2 59.51,32.404 59.489,32.404 59.418,32.475
  Signal Layer 4 w0.1: v2(59.7,28.643) 59.7,28.687 59.481,28.905 59.481,30.502 59.868,30.889 59.868,32.157 v2(59.825,32.2)
  other v2: 59.375,34.125
N16916616: U810.8 U812.8 U862.4 | length 14.5
  Top Layer w0.1: U862.4@53.475,39.45 53.725,39.45 v2(53.975,39.2) ; U812.8@58.575,31.835 58.59,31.85 v2(59.05,31.85) 59.093,31.807 60.192,31.807 60.625,31.374 60.625,31.05 60.325,30.75 U810.8@60.125,30.75
  Signal Layer 4 w0.1: v2(53.975,39.2) 54.589,38.586 54.589,36.542 54.578,36.531 54.578,34.479 55.091,33.966 v1(55.143,33.966)
  Bottom Layer w0.1: v1(55.143,33.966) 56.147,32.962 56.147,32.778 57.075,31.85 v2(59.05,31.85)
N16917071: R882.1 U860.3 | length 2.6
  Top Layer w0.1: U860.3@48.374,45.359 48.374,45.616 48.433,45.675 50.32,45.675 50.595,45.4 R882.1@50.6,45.4
N16922979: R601.1 R602.2 U600.5 | length 1.7
  Top Layer w0.127: U600.5@24.15,46.075 24.56,46.075 24.79,46.305 R601.1@25.162,46.305 25.162,46.838 R602.2@25.15,46.85
N16923003: R600.1 U600.7 | length 0.8
  Top Layer w0.127: R600.1@22.937,46.83 22.947,46.83 23.043,46.734 23.043,46.724 23.137,46.63 23.137,46.088 U600.7@23.15,46.075
N16923019: C602.1 U600.6 | length 0.9
  Top Layer w0.127: U600.6@23.637,46.08 23.637,46.68 23.67,46.714 23.67,46.734 C602.1@23.761,46.825 ; C602.1@23.787,46.83 23.767,46.83 C602.1@23.761,46.825 ; C602.1@23.8,46.825 C602.1@23.761,46.825
N16923678: Q602.6 R674.1 R675.1 U606.3 | length 6.5
  Top Layer w0.2: Q602.6@46.375,26.875 46.377,26.877 46.377,27.238 46.529,27.39 47.038,27.39 47.155,27.507 47.155,27.69 47.215,27.75 47.295,27.75 47.526,27.75 47.712,27.564 48.297,27.564 R675.1@48.312,27.549
  Top Layer w0.3: U606.3@42.8,27.525 45.075,27.525 45.725,26.875 Q602.6@46.375,26.875
N16923728: Q601.4 R628.1 R672.2 | length 1.8
  Top Layer w0.3: R628.1@39.025,28 R628.1@39.075,27.95 ; Q601.4@39.075,27 R628.1@39.075,27.95 ; R672.2@39.825,27.95 39.825,27.96 39.815,27.97 39.095,27.97 R628.1@39.075,27.95
N16923751: Q602.3 R687.1 R688.1 U622.3 | length 11
  Top Layer w0.3: Q602.3@47.375,25.575 48.4,25.575 R687.1@48.45,25.625 48.475,25.65 48.475,26.05 48.751,26.326 49.873,26.326 50.475,26.929 50.475,29.411 50.236,29.65 50.236,30.274 50.58,30.617 50.58,30.715 50.59,30.725 R688.1@50.6,30.725 ; R688.1@50.75,30.865 50.75,32.475 51.275,33 U622.3@52.025,33
N16923761: Q602.5 R686.2 | length 12.5
  Top Layer w0.3: Q602.5@46.875,26.875 46.875,26.532 v1(47.172,26.236) ; v1(50.589,24.98) 50.594,24.975 53.1,24.975 53.95,25.825 53.95,26.675 52.375,28.25 52.375,29.05 R686.2@52.225,29.2
  Bottom Layer w0.3: v1(47.172,26.236) 47.782,25.625 49.944,25.625 v1(50.589,24.98)
N16923771: C653.1 R629.1 U622.4 | length 3.8
  Top Layer w0.2: U622.4@50.125,33 50.775,33 51.275,33.5 52.295,33.5 52.907,32.888 C653.1@52.91,32.888
  Top Layer w0.3: C653.1@52.91,32.888 53.44,32.888 53.45,32.898 R629.1@53.45,32.9
N16923807: R686.1 U622.1 | length 1.7
  Top Layer w0.3: U622.1@52.025,31.7 52.05,31.7 52.1,31.65 52.1,30.225 R686.1@52.225,30.1
N16923899: C652.1 R690.1 U622.5 | length 2.9
  Top Layer w0.3: R690.1@49.075,30.65 48.935,30.79 48.935,32.075 49.3,32.075 49.625,31.75 50.075,31.75 U622.5@50.125,31.7 U622.5@50.1,31.675
N16923917: C660.1 R681.1 U606.5 | length 2
  Top Layer w0.3: U606.5@40.9,26.225 C660.1@40.9,25.25 40.91,25.24 41.835,25.24 R681.1@41.9,25.175
N16923949: Q602.2 R679.2 | length 2.6
  Top Layer w0.1: R679.2@44.9,26.675 45.285,26.29 46.51,26.29 46.834,25.966 46.834,25.616 Q602.2@46.875,25.575
N16923963: C621.1 R672.1 U606.4 | length 2.7
  Top Layer w0.3: C621.1@39.825,26.475 C621.1@39.825,26.49 ; R672.1@39.825,27.3 C621.1@39.825,26.49 ; U606.4@40.9,27.525 40.85,27.475 40.476,27.475 40.3,27.299 40.3,26.681 40.124,26.505 39.835,26.505 39.825,26.495 C621.1@39.825,26.49
N16924927: Q600.3 Q600.6 | length 3
  Top Layer w0.3: v2(35.514,26.586) 35.551,26.623 36.013,26.623 Q600.6@36.013,26.66 ; Q600.3@37.013,25.36 37.013,26.001 v1(37.022,26.01)
  Signal Layer 4 w0.5: v2(35.514,26.586) 35.516,26.584 36.448,26.584 v1(37.022,26.01)
N16934878: C900.1 U900.J13 | length 1.9
  Top Layer w0.2: C900.1@38.025,42.6 38.026,42.574 38.325,42.275 38.425,42.275 38.442,42.258 39.204,42.258 39.437,42.025 U900.J13@39.675,42.025
N16934900: C903.1 C904.1 C905.1 C906.1 R130.2 U900.M9 U900.M10 U900.N11 | length 7.8
  Top Layer w0.2: C906.1@39.749,46.494 39.749,46.962 ; 40.675,44.625 U900.N11@40.675,44.025 U900.M10@41.175,43.525 U900.M9@41.675,43.525
  Top Layer w0.3: C906.1@39.749,46.494 C905.1@39.749,45.945 C904.1@39.749,45.369 39.769,45.369 40.151,44.987 40.263,44.987 40.625,44.625
  Top Layer w0.5: C903.1@38.075,47.4 39.45,47.4 39.634,47.216 39.634,46.964 39.747,46.851
  Top Layer w0.635: R130.2@36.925,47.4 C903.1@38.075,47.4
N16936696: U900.N10 X900.1 | length 1.8
  Top Layer w0.2: X900.1@40.975,45.75 40.975,44.225 U900.N10@41.175,44.025
N16936699: U900.N9 X900.3 | length 3.4
  Top Layer w0.2: U900.N9@41.675,44.025 41.599,44.025 41.386,44.238 41.386,44.886 41.675,45.175 41.675,46.184 42.341,46.85 X900.3@42.375,46.85
N16939106: TPJ909.1 U900.C11 | length 9.2
  Top Layer w0.1: v2(38.885,38.735) 38.925,38.775 40.425,38.775 U900.C11@40.675,39.025
  Bottom Layer w0.1: v2(38.885,38.735) 38.807,38.813 38.807,39.053 38.725,39.135 38.725,39.476 39.166,39.917 39.467,39.917 39.725,40.175 39.725,41.325 40.575,42.175 40.874,42.175 40.879,42.18 41.405,42.18 41.518,42.293 41.859,42.293 42.169,42.602 42.169,42.944 TPJ909.1@42.65,43.425
N16939109: TPJ910.1 U900.D11 | length 16.7
  Top Layer w0.1: v2(39.118,39.298) 39.11,39.29 39.125,39.275 40.425,39.275 U900.D11@40.675,39.525
  Bottom Layer w0.1: v2(39.118,39.298) 41.19,37.225 41.999,37.225 42.4,36.824 42.818,36.405 42.818,36.268 46.287,32.8 47.6,32.8 48.496,31.904 48.496,30.896 48,30.4 TPJ910.1@48,29.65
N16939489: TPJ911.1 U900.F11 | length 14.7
  Top Layer w0.1: U900.F11@40.675,40.525 40.886,40.314 v2(42.1,40.314)
  Signal Layer 4 w0.1: v2(42.1,40.314) 42.094,40.319 41.707,39.932 41.707,38.118 42.468,37.357 42.468,35.132 44.75,32.85 v2(44.75,30.45)
  Bottom Layer w0.1: v2(44.75,30.45) 45.45,29.75 TPJ911.1@45.45,28.85
N16939638: TPJ900.1 U900.A2 | length 8.8
  Top Layer w0.1: U900.A2@45.175,38.025 45.175,37.031 45.741,36.466 45.947,36.259 45.947,35.803 46.07,35.68 46.07,35.35 v2(46.086,35.334)
  Bottom Layer w0.1: TPJ900.1@41.607,37.9 42.27,37.237 42.6,36.907 43.018,36.488 43.018,36.464 43.018,36.409 44.305,35.122 44.897,35.122 45.109,35.334 v2(46.086,35.334)
N16939640: TPJ901.1 U900.A1 | length 3.6
  Top Layer w0.1: U900.A1@45.675,37.966 45.675,37.346 45.934,37.088 45.934,37.072 v2(45.972,37.072)
  Bottom Layer w0.1: TPJ901.1@44.05,38.55 45.53,37.07 45.905,37.07 45.925,37.05 45.947,37.072 v2(45.972,37.072)
N16940103: TPJ908.1 U900.A9 | length 17.6
  Top Layer w0.1: v2@40.781,36.128 40.786,36.134 40.786,36.466 40.827,36.507 40.827,36.839 ; 40.96,36.971 40.827,36.839 ; U900.A9@41.675,38.025 41.675,37.687 40.827,36.839
  Bottom Layer w0.1: v2(40.786,36.123) 40.786,37.253 39.816,38.223 38.777,38.223 38.489,38.511 38.489,39.301 38.525,39.337 38.525,40.85 39.025,41.35 39.154,41.35 39.475,41.671 39.475,44.2 40.225,44.95 42.025,44.95 42.485,45.41 43.441,45.41 43.46,45.428 43.778,45.428 TPJ908.1@43.95,45.6
N16942491: R902.2 U900.B13 | length 1.9
  Top Layer w0.12: R902.2@38.075,38.75 38.493,38.332 39.472,38.332 39.666,38.525 U900.B13@39.675,38.525
N16942503: R904.2 U900.A13 | length 1.7
  Top Layer w0.12: R904.2@38.075,37.875 38.292,38.092 39.587,38.092 39.653,38.025 U900.A13@39.675,38.025
N16943456: TPJ902.1 U900.A8 | length 20.9
  Top Layer w0.1: v2(42.007,36.66) 41.95,36.717 41.95,37.375 42.175,37.6 U900.A8@42.175,38.025
  Signal Layer 3 w0.1: v1(25.254,40.644) 34.906,40.644 36.325,39.225 37.425,39.225 38.6,38.05 40.618,38.05 v2@42.007,36.661
  Bottom Layer w0.1: TPJ902.1@24.6,41.4 24.6,41.298 v1(25.254,40.644)
N16944010: LED903.2 R912.2 | length 0.7
  Top Layer w0.305: LED903.2@16.325,43.5 16.325,42.875 16.382,42.818 16.382,42.808 16.39,42.8 R912.2@16.4,42.8
N16966205: LED904.2 R920.2 | length 0.9
  Top Layer w0.1: R920.2@15.222,46.215 15.237,46.2 15.425,46.2 15.435,46.21 LED904.2@16.139,46.21
N16966207: LED904.1 R919.2 | length 0.9
  Top Layer w0.1: R919.2@15.222,45.531 15.228,45.525 15.45,45.525 15.465,45.51 LED904.1@16.139,45.51
N16966211: LED901.1 R903.2 | length 3.3
  Top Layer w0.1: LED901.1@4.525,45.125 4.525,45.538 4.912,45.925 6.225,45.925 6.6,45.55 R903.2@6.6,45.1
N16966215: LED900.1 R900.2 | length 1.3
  Top Layer w0.1: R900.2@89.25,54.3 LED900.1@89.25,55.55
N16996446: Q807.5 Q807.6 R838.1 | length 2
  Top Layer w0.1: Q807.6@53.8,29.9 53.787,29.913 52.987,29.913 R838.1@52.975,29.925 52.975,30.245 53.13,30.4 Q807.5@53.8,30.4
N16997087: Q807.2 R839.2 R841.1 | length 2.5
  Top Layer w0.1: R841.1@54.411,28.445 54.443,28.477 54.443,29.093 R839.2@54.475,29.125 54.475,30.2 54.675,30.4 Q807.2@55.1,30.4
N17012885: L900.2 R130.1 | length 3.3
  Top Layer w0.5: L900.2@32.69,47.55 35.875,47.55 R130.1@35.975,47.45
N17206837: C198.1 L100.1 R197.2 | length 4.9
  Top Layer w0.127: R197.2@106.677,10.8 106.933,10.544 C198.1@107.568,10.544 107.568,10.564 108.129,11.125 L100.1@111.222,11.125
N17206841: L100.2 R195.1 R196.2 | length 4.8
  Top Layer w0.127: R196.2@107.568,7.293 107.568,8.171 R195.1@107.572,8.175 108.322,8.925 L100.2@111.222,8.925
N17206845: C198.2 R195.2 | length 0.9
  Top Layer w0.3: C198.2@107.568,9.994 107.57,9.992 107.57,9.077 R195.2@107.572,9.075
N17206847: C199.1 R197.1 R198.2 | length 1.5
  Top Layer w0.127: R197.1@106.677,9.9 106.7,9.877 C199.1@106.7,9.126 106.7,8.397 R198.2@106.722,8.375
N17234269: C200.1 R246.2 | length 1.2
  Top Layer w0.3: C200.1@99.2,25 99.2,26.15 R246.2@99.25,26.2
N17262372: C729.1 R718.2 U703.4 U704.3 U704.5 | length 9.9
  Top Layer w0.1: U704.3@28.42,40.675 30.227,40.675 30.877,40.025 U704.5@32.631,40.025 32.631,39.627 32.325,39.321 32.325,38.325 32.983,37.667 32.983,37.124 33.057,37.05 U703.4@33.125,37.05 C729.1@33.9,37.05 33.9,37.07 34.28,37.45 R718.2@34.925,37.45
N17262509: R709.1 U703.1 U703.2 | length 3.2
  Top Layer w0.1: R709.1@32.832,34 33.147,34.315 33.147,35.528 U703.1@33.125,35.55 33.163,35.588 33.537,35.588 33.687,35.738 33.687,35.96 33.597,36.05 U703.2@33.125,36.05
N17262517: C710.2 U703.6 | length 0.8
  Top Layer w0.25: C710.2@29.525,36.575 29.55,36.55 U703.6@30.325,36.55
N17262549: R710.1 U703.8 | length 2.2
  Top Layer w0.1: U703.8@30.325,35.55 30.325,34.975 R710.1@31.3,34
  Top Layer w0.127: R710.1@31.3,34 R710.1@31.59,34
N17262561: L700.2 R717.1 | length 1
  Top Layer w0.5: L700.2@27.525,33.9 R717.1@28.475,33.9
N17262689: C766.1 R765.1 R767.2 U704.2 | length 3.1
  Top Layer w0.1: R767.2@26.675,39.55 R765.1@26.675,40.6 27.1,41.025 C766.1@27.575,41.025 27.875,41.325 U704.2@28.42,41.325
N17262695: C766.2 R764.1 R765.2 U704.1 | length 3.4
  Top Layer w0.1: R764.1@26.6,43.275 26.6,42.075 R765.2@26.675,42 27.1,41.575 C766.2@27.575,41.575 27.575,41.595 27.685,41.705 27.705,41.705 27.884,41.884 28.328,41.884 U704.1@28.42,41.975
N17262717: C770.1 R769.1 R771.2 U704.6 | length 3.5
  Top Layer w0.1: U704.6@32.631,40.675 33.35,40.675 C770.1@33.475,40.8 33.475,40.78 33.585,40.67 33.605,40.67 33.863,40.412 34.063,40.412 R769.1@34.375,40.1 33.816,39.541 33.816,39.141 R771.2@33.675,39
N17262723: C770.2 R768.1 R769.2 U704.7 | length 2.8
  Top Layer w0.1: U704.7@32.631,41.325 32.656,41.35 C770.2@33.475,41.35 34.225,41.35 R769.2@34.375,41.5 R768.1@34.375,42.5
N17263058: C730.1 C731.1 R731.1 U704.8 | length 3.9
  Top Layer w0.5: R731.1@31.125,44.9 31.6,44.9 32.575,43.925 C731.1@32.575,43.8 32.63,43.745 32.63,42.031 32.575,42.031 U704.8@32.631,41.975
N17263074: L704.2 R731.2 | length 0.9
  Top Layer w0.5: L704.2@30.15,45.8 30.15,44.975 R731.2@30.225,44.9
N17356200: Q800.2 R815.1 | length 1.9
  Top Layer w0.1: R815.1@57.276,39.006 57.276,38.996 57.605,38.667 57.605,38.57 57.825,38.35 58.175,38.35 58.5,38.675 Q800.2@58.5,38.85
